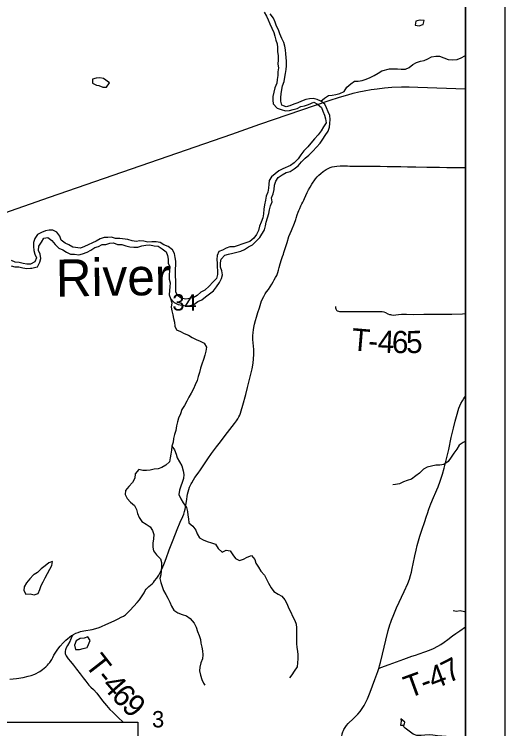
# Model space of a CAD drawing. Extents: x -7.5 to 53.5, y 0 to 22.
# Drawn here: x 7.745 to 9, y 16.725 to 18.553 of the extents above; entities that cross this region are included whole.
import ezdxf

# ---------------------------------------------------------------- set-up
doc = ezdxf.new("R2010")
doc.units = 0
for name, color, linetype in [('GM_X_Corporation', 7, 'Continuous'), ('GM_X_Major_River', 7, 'Continuous'), ('GM_X_Major_River_Text', 7, 'Continuous'), ('GM_X_Minor_Lake', 7, 'Continuous'), ('GM_X_Minor_River', 7, 'Continuous'), ('GM_X_Rail_Line', 7, 'Continuous'), ('GM_X_Section_Text', 7, 'Continuous'), ('GM_X_Township_Road', 7, 'Continuous'), ('GM_X_Township_Road_Text', 7, 'Continuous'), ('SH_Data', 7, 'Continuous'), ('SH_Text', 7, 'Continuous')]:
    doc.layers.add(name, color=color, linetype=linetype)

msp = doc.modelspace()

# ---------------------------------------------------------------- linework, layer by layer
at = {"layer": 'GM_X_Corporation'}
msp.add_lwpolyline([(8.9, 14.1), (8.9, 19.1887), (8.5159, 19.1718), (8.414, 19.1709), (7.544, 19.1455), (6.5522, 19.1561), (6.0433, 19.1527), (6.0424, 19.1527), (5.0411, 19.1401), (4.5565, 19.1354), (4.5696, 18.2604), (4.5718, 18.1276), (4.5771, 17.6201), (4.5749, 17.2575), (4.577, 17.1178), (4.5822, 16.8992), (4.5826, 16.8462), (4.5872, 16.3635), (4.5873, 16.3533), (4.594, 15.8096), (4.6021, 15.6139), (4.6087, 14.5302)], dxfattribs=at)
at = {"layer": 'GM_X_Major_River'}
for points in [[(8.3844, 18.5588), (8.3904, 18.5489), (8.3949, 18.5394), (8.399, 18.5287), (8.4038, 18.5181), (8.4094, 18.507), (8.4112, 18.4975), (8.4138, 18.4876), (8.4171, 18.4778), (8.4182, 18.4683), (8.4181, 18.458), (8.4203, 18.447), (8.4202, 18.4371), (8.4193, 18.4258), (8.4208, 18.4163), (8.4188, 18.4061), (8.4195, 18.3966), (8.4175, 18.3867), (8.4163, 18.3769), (8.4116, 18.3656), (8.4093, 18.3546), (8.4061, 18.3432), (8.4064, 18.3337), (8.4075, 18.3243), (8.4173, 18.3135), (8.4278, 18.3097), (8.4388, 18.3065), (8.4491, 18.3076), (8.4586, 18.3098), (8.4684, 18.3123), (8.4783, 18.3172), (8.4878, 18.3194), (8.4981, 18.3223), (8.511, 18.3282), (8.5208, 18.3236), (8.5314, 18.3148), (8.5347, 18.3053), (8.5384, 18.2954), (8.541, 18.2859), (8.5432, 18.276), (8.5363, 18.2658), (8.5301, 18.2553), (8.5224, 18.2451), (8.5129, 18.2349), (8.5037, 18.224), (8.4957, 18.2139), (8.4861, 18.2041), (8.4777, 18.1939), (8.4715, 18.1834), (8.4608, 18.1732), (8.4513, 18.1669), (8.4323, 18.1579), (8.422, 18.1527), (8.4125, 18.1456), (8.4029, 18.1377), (8.3968, 18.1279), (8.3963, 18.1184), (8.3955, 18.1082), (8.3939, 18.0984), (8.3896, 18.0878), (8.3876, 18.0779), (8.3853, 18.0662), (8.3833, 18.0545), (8.3828, 18.0431), (8.3812, 18.0325), (8.3769, 18.0215), (8.3727, 18.011), (8.3699, 18), (8.3646, 17.9902), (8.3577, 17.9804), (8.3474, 17.9725), (8.3371, 17.9684), (8.3268, 17.9655), (8.3173, 17.9622), (8.3078, 17.9584), (8.2964, 17.9582), (8.2869, 17.9552), (8.2774, 17.95), (8.2679, 17.9467), (8.264, 17.9361), (8.2632, 17.9262), (8.2639, 17.9168), (8.2642, 17.9069), (8.2649, 17.8974), (8.2652, 17.8875), (8.2624, 17.8777), (8.2532, 17.8679), (8.2433, 17.8578), (8.2326, 17.8473), (8.2223, 17.8424), (8.2128, 17.8342), (8.2025, 17.8282), (8.1835, 17.8246), (8.1722, 17.8269), (8.162, 17.8339), (8.1579, 17.8434), (8.158, 17.8529), (8.1584, 17.8623), (8.1578, 17.873), (8.1571, 17.8824)], [(8.5531, 18.2843), (8.5524, 18.2941), (8.548, 18.3036), (8.5435, 18.3139), (8.5398, 18.3234), (8.5296, 18.3311), (8.5198, 18.335), (8.51, 18.3381), (8.5001, 18.3371), (8.4906, 18.3353), (8.48, 18.3308), (8.4701, 18.3271), (8.4602, 18.3238), (8.4503, 18.3193), (8.4408, 18.3167), (8.4298, 18.3206), (8.4265, 18.3309), (8.4273, 18.3404), (8.4278, 18.3499), (8.4298, 18.3608), (8.4314, 18.3707), (8.4353, 18.3816), (8.4369, 18.3922), (8.4385, 18.4021), (8.4408, 18.4119), (8.4413, 18.4218), (8.4414, 18.4335), (8.4407, 18.443), (8.4393, 18.4525), (8.439, 18.4624), (8.4368, 18.4719), (8.4342, 18.4814), (8.4297, 18.4917), (8.4242, 18.5035), (8.4212, 18.5134), (8.416, 18.5233), (8.4123, 18.5332), (8.4078, 18.5434), (8.3996, 18.5549)], [(7.8406, 17.9748), (7.8489, 17.9645), (7.8586, 17.9549), (7.8685, 17.9507), (7.8783, 17.9445), (7.8888, 17.9395), (7.8987, 17.9394), (7.9097, 17.9378), (7.9192, 17.9407), (7.9313, 17.9452), (7.9408, 17.9496), (7.9504, 17.9564), (7.9599, 17.9593), (7.9694, 17.9645), (7.9792, 17.9641), (7.9891, 17.9682), (7.9986, 17.9688), (8.0092, 17.9646), (8.0198, 17.9641), (8.03, 17.9606), (8.0406, 17.9586), (8.0505, 17.9577), (8.0611, 17.958), (8.0709, 17.9613), (8.0816, 17.9624), (8.0918, 17.9634), (8.1028, 17.9607), (8.1126, 17.9598), (8.1232, 17.9537), (8.133, 17.946), (8.1367, 17.9365), (8.1381, 17.9266), (8.1388, 17.9164), (8.1425, 17.9069), (8.1417, 17.8974), (8.1408, 17.8868), (8.1407, 17.8758), (8.1437, 17.8663), (8.1429, 17.8564), (8.1416, 17.8466), (8.1408, 17.836), (8.1445, 17.8261), (8.1539, 17.8161), (8.1641, 17.8111), (8.1747, 17.8091), (8.1845, 17.8075), (8.1944, 17.8085), (8.2039, 17.8111), (8.2145, 17.8182), (8.2244, 17.8231), (8.2344, 17.8302), (8.2542, 17.8459), (8.2622, 17.8565), (8.2695, 17.8674), (8.2749, 17.8772), (8.2773, 17.8871), (8.2758, 17.8973), (8.2721, 17.9068), (8.2726, 17.9171), (8.2742, 17.9273), (8.2838, 17.9367), (8.2933, 17.9396), (8.3043, 17.9426), (8.3145, 17.9451), (8.3244, 17.9473), (8.3343, 17.9518), (8.3438, 17.9581), (8.3541, 17.9637), (8.3637, 17.9731), (8.3732, 17.9821), (8.3847, 18.0017), (8.3875, 18.012), (8.3891, 18.0218), (8.3926, 18.0328), (8.3965, 18.0433), (8.3981, 18.0532), (8.4004, 18.0634), (8.4043, 18.0732), (8.4029, 18.0842), (8.4075, 18.0944), (8.4099, 18.1054), (8.4103, 18.116), (8.4142, 18.1262), (8.4203, 18.136), (8.4299, 18.1424), (8.4409, 18.1484), (8.4504, 18.1513), (8.4611, 18.1577), (8.471, 18.1659), (8.4794, 18.1757), (8.489, 18.1855), (8.4985, 18.1934), (8.5088, 18.2031), (8.518, 18.2137), (8.5272, 18.2234), (8.5345, 18.2336), (8.5406, 18.2434), (8.5479, 18.2543), (8.5518, 18.2649), (8.5523, 18.2744), (8.5531, 18.2843)], [(7.9539, 17.973), (7.9444, 17.9686), (7.9338, 17.9637), (7.9242, 17.9589), (7.9144, 17.9552), (7.8947, 17.9576), (7.8845, 17.9638), (7.8747, 17.9677), (7.8645, 17.9757), (7.8615, 17.9856), (7.8537, 17.9959), (7.8435, 18.0013), (7.834, 18.001), (7.8245, 17.9992), (7.8139, 17.9955), (7.8043, 17.9899), (7.7974, 17.9801), (7.7936, 17.9699), (7.7939, 17.9589), (7.7949, 17.9494), (7.7971, 17.9399), (7.8016, 17.9304), (7.7973, 17.9202), (7.7863, 17.9142), (7.7768, 17.9139), (7.767, 17.9159), (7.7571, 17.9183), (7.7469, 17.9195), (7.7371, 17.9234)], [(7.7995, 17.9062), (7.8037, 17.9076), (7.8098, 17.919), (7.8122, 17.9288), (7.8111, 17.9398), (7.8063, 17.9493), (7.8071, 17.9603), (7.814, 17.9705), (7.8206, 17.9807), (7.8301, 17.9825), (7.8406, 17.9748)], [(8.1571, 17.8824), (8.1575, 17.8919), (8.1576, 17.9014), (8.1585, 17.912), (8.1582, 17.9219), (8.156, 17.9314), (8.1545, 17.9413), (8.1493, 17.9508), (8.1384, 17.9596), (8.1278, 17.9639), (8.118, 17.9693), (8.1078, 17.9713), (8.0968, 17.971), (8.0862, 17.9707), (8.076, 17.9731), (8.0657, 17.9735), (8.0563, 17.9717), (8.046, 17.9737), (8.0351, 17.9772), (8.0146, 17.9797), (8.0036, 17.9798), (7.9938, 17.9829), (7.9843, 17.9826), (7.9745, 17.9819), (7.9646, 17.9786), (7.9539, 17.973)], [(7.7366, 17.9094), (7.7464, 17.9074), (7.7563, 17.9069), (7.7661, 17.9046), (7.7767, 17.903), (7.7862, 17.9036), (7.7873, 17.904)], [(7.7873, 17.904), (7.7892, 17.9036), (7.7995, 17.9062)]]:
    msp.add_lwpolyline(points, dxfattribs=at)
at = {"layer": 'GM_X_Minor_Lake'}
for points in [[(8.7826, 18.5385), (8.7727, 18.5356), (8.7708, 18.5258), (8.7806, 18.5241), (8.7901, 18.5271), (8.7909, 18.5275)], [(8.7909, 18.5275), (8.794, 18.5373), (8.7838, 18.5385), (8.7826, 18.5385)], [(7.9733, 18.3892), (7.9635, 18.3908), (7.954, 18.3902), (7.9445, 18.3872), (7.9448, 18.3774), (7.955, 18.3723), (7.961, 18.3715)], [(7.961, 18.3715), (7.9712, 18.3669), (7.9807, 18.3668), (7.988, 18.3777), (7.9733, 18.3892)], [(7.8097, 17.0813), (7.8136, 17.0918), (7.8182, 17.1017), (7.8236, 17.1115), (7.8294, 17.1228), (7.8355, 17.1334), (7.8409, 17.1432), (7.8425, 17.153), (7.833, 17.1501), (7.8235, 17.1426), (7.8132, 17.1347), (7.8044, 17.1249), (7.7956, 17.1197)], [(7.7956, 17.1197), (7.7937, 17.1189), (7.7842, 17.1092), (7.7761, 17.099), (7.7703, 17.0888), (7.7688, 17.079), (7.774, 17.0695), (7.7854, 17.0705), (7.7956, 17.0681), (7.8058, 17.0714), (7.8097, 17.0813)], [(7.9129, 16.9563), (7.9034, 16.95), (7.8984, 16.939), (7.9013, 16.9284), (7.9115, 16.9283), (7.921, 16.9305), (7.9309, 16.9334), (7.9321, 16.9349)], [(7.9321, 16.9349), (7.9386, 16.9512), (7.933, 16.9607), (7.9231, 16.9574), (7.9129, 16.9563)], [(8.7344, 16.7506), (8.7351, 16.7445), (8.7332, 16.7347), (8.7426, 16.7346)], [(8.7426, 16.7346), (8.7442, 16.7425), (8.7344, 16.7506)]]:
    msp.add_lwpolyline(points, dxfattribs=at)
at = {"layer": 'GM_X_Minor_River'}
for points in [[(8.5296, 18.3311), (8.5391, 18.339), (8.5487, 18.3454), (8.5582, 18.3464), (8.5677, 18.3478), (8.5783, 18.3508), (8.5886, 18.356), (8.5962, 18.3673), (8.6058, 18.3759), (8.6153, 18.3823), (8.6248, 18.3826), (8.6354, 18.3844), (8.6453, 18.3873), (8.6556, 18.3914), (8.6658, 18.397), (8.6761, 18.4026), (8.6857, 18.409), (8.7047, 18.4141), (8.7156, 18.4136), (8.7255, 18.4135), (8.7353, 18.4131), (8.7456, 18.413), (8.7551, 18.4171), (8.765, 18.4246), (8.7745, 18.4302), (8.784, 18.4335), (8.7935, 18.4353), (8.8034, 18.4398), (8.8129, 18.4446), (8.8236, 18.4464), (8.833, 18.4463), (8.8444, 18.442), (8.8553, 18.4381), (8.8667, 18.4369), (8.8781, 18.4379), (8.8883, 18.4424), (8.8979, 18.4472), (8.9, 18.4475)], [(8.1445, 17.8261), (8.1478, 17.8154), (8.1466, 17.8044), (8.1476, 17.7946), (8.1502, 17.7847), (8.152, 17.7748), (8.1546, 17.7653), (8.1557, 17.7558), (8.1598, 17.7463), (8.17, 17.742), (8.1798, 17.737), (8.1903, 17.7327), (8.2001, 17.7266), (8.2103, 17.7212), (8.2205, 17.7169), (8.2307, 17.7119), (8.2367, 17.702), (8.2351, 17.6918), (8.232, 17.6815), (8.2289, 17.6702), (8.2246, 17.6585), (8.2215, 17.6479), (8.2184, 17.6365), (8.2152, 17.6263), (8.2125, 17.6165), (8.2079, 17.6055), (8.2036, 17.595), (8.1974, 17.5836), (8.1913, 17.5738), (8.1863, 17.5633), (8.1805, 17.5523), (8.1736, 17.5418), (8.1697, 17.5312), (8.1651, 17.5202), (8.162, 17.5104), (8.1596, 17.5006), (8.158, 17.4884), (8.1545, 17.4782), (8.1521, 17.4684), (8.1513, 17.4589), (8.1482, 17.4483), (8.1473, 17.4381), (8.145, 17.4283), (8.1434, 17.4184), (8.1422, 17.4086), (8.1322, 17.3999), (8.1227, 17.3939), (8.1125, 17.3902), (8.1026, 17.3892), (8.0927, 17.3874), (8.0829, 17.3863), (8.0734, 17.3864), (8.0635, 17.3884), (8.0544, 17.3779), (8.0528, 17.3665), (8.0474, 17.3556), (8.0374, 17.3454), (8.0297, 17.3349), (8.0281, 17.3246), (8.0334, 17.3147), (8.042, 17.3052), (8.0525, 17.2964), (8.0574, 17.2865), (8.06, 17.2758), (8.064, 17.2655), (8.0708, 17.256), (8.0821, 17.2487), (8.0927, 17.2421), (8.0983, 17.2322), (8.1016, 17.2223), (8.1007, 17.211), (8.0991, 17.2004), (8.0994, 17.1901), (8.1012, 17.1806), (8.1087, 17.17), (8.1185, 17.1604), (8.1215, 17.1509), (8.1214, 17.1406), (8.1205, 17.1304), (8.1197, 17.1194), (8.117, 17.1096), (8.1195, 17.0993), (8.1228, 17.0894), (8.1266, 17.0795), (8.1325, 17.0692), (8.1374, 17.0597), (8.143, 17.0491), (8.1474, 17.0392), (8.153, 17.0289), (8.1632, 17.0223), (8.1746, 17.0177), (8.1851, 17.0142), (8.1949, 17.0072), (8.2047, 16.9958), (8.2099, 16.9851), (8.2132, 16.9745), (8.2181, 16.9638), (8.221, 16.9535), (8.2221, 16.9441), (8.225, 16.9345), (8.2265, 16.9251)], [(8.9, 17.461), (8.8934, 17.4579), (8.8835, 17.4508), (8.8774, 17.441), (8.8697, 17.4304), (8.8632, 17.4199), (8.8551, 17.4089), (8.8445, 17.4018), (8.8342, 17.4), (8.824, 17.3994), (8.8126, 17.3972), (8.8019, 17.3946), (8.792, 17.3894), (8.7817, 17.3796), (8.7722, 17.3725), (8.7611, 17.3639), (8.7505, 17.3606), (8.7406, 17.3569), (8.7307, 17.3517), (8.7208, 17.3499), (8.714, 17.3492)], [(8.1482, 17.4483), (8.1549, 17.4388), (8.159, 17.4281), (8.1616, 17.4186), (8.1679, 17.4087), (8.1735, 17.3977), (8.1772, 17.3855), (8.1787, 17.376), (8.1778, 17.3658), (8.1747, 17.3556), (8.1712, 17.3457), (8.1673, 17.3355), (8.1654, 17.3245), (8.1709, 17.3135), (8.1773, 17.3036), (8.1852, 17.2914), (8.1881, 17.2815), (8.1892, 17.2716), (8.1906, 17.2621), (8.1917, 17.2526), (8.2018, 17.2434), (8.2097, 17.2339), (8.213, 17.224), (8.2186, 17.2141), (8.2284, 17.2087), (8.2387, 17.2048), (8.2492, 17.2013), (8.2594, 17.1974), (8.2669, 17.1863), (8.2767, 17.1772), (8.287, 17.182), (8.2968, 17.1808), (8.3039, 17.1705), (8.3111, 17.1609), (8.3209, 17.1559), (8.3315, 17.1596), (8.341, 17.1648), (8.3517, 17.1685), (8.3607, 17.1586), (8.3629, 17.1491), (8.3696, 17.1392), (8.376, 17.1289), (8.3854, 17.1182), (8.3902, 17.1083), (8.3951, 17.098), (8.4018, 17.0862), (8.4093, 17.0766), (8.4198, 17.0701), (8.4297, 17.0647), (8.4375, 17.0551), (8.4428, 17.0444), (8.4468, 17.0349), (8.4521, 17.0235), (8.4565, 17.0136), (8.4625, 17.0026), (8.4658, 16.993), (8.4669, 16.9832), (8.4672, 16.9733), (8.4667, 16.9638), (8.4666, 16.9536), (8.4669, 16.9434), (8.468, 16.9331), (8.4694, 16.9236), (8.4701, 16.9141), (8.4704, 16.9043), (8.4696, 16.8944), (8.4691, 16.8834), (8.4614, 16.8729), (8.4549, 16.8631), (8.4491, 16.8555)], [(8.9, 17.0248), (8.897, 17.0248), (8.8861, 17.0272), (8.8762, 17.0257), (8.8679, 17.027)], [(8.2265, 16.9251), (8.2275, 16.9144), (8.2267, 16.9042), (8.2221, 16.894), (8.2193, 16.8826), (8.2185, 16.8732), (8.2214, 16.8621), (8.2247, 16.8515), (8.2288, 16.8416), (8.2322, 16.8366)], [(8.9, 16.7003), (8.8936, 16.6998), (8.8822, 16.6996), (8.8724, 16.7004), (8.861, 16.7032), (8.8504, 16.7059), (8.8387, 16.706), (8.8277, 16.7076), (8.8163, 16.7093), (8.8065, 16.7097), (8.7959, 16.7091), (8.7864, 16.708), (8.7754, 16.7081), (8.7656, 16.7112), (8.755, 16.7193), (8.7452, 16.7266), (8.738, 16.7346)]]:
    msp.add_lwpolyline(points, dxfattribs=at)
at = {"layer": 'GM_X_Rail_Line'}
msp.add_lwpolyline([(7.7029, 18.0394), (7.835, 18.0853), (8.3014, 18.2469), (8.3734, 18.2719), (8.5509, 18.3328), (8.577, 18.3414), (8.598, 18.3475), (8.612, 18.3512), (8.6268, 18.3548), (8.6406, 18.3578), (8.6579, 18.3607), (8.6735, 18.363), (8.6921, 18.3652), (8.7109, 18.3666), (8.7359, 18.3675), (8.7554, 18.3676), (8.7774, 18.3673), (8.9, 18.363)], dxfattribs=at)
at = {"layer": 'GM_X_Township_Road'}
for points in [[(7.8933, 16.9648), (7.8965, 16.9668), (7.902, 16.9696), (7.9077, 16.972), (7.9137, 16.9738), (7.9227, 16.9759), (7.9442, 16.9795), (7.9533, 16.9815), (7.9622, 16.9843), (7.9679, 16.9866), (7.9791, 16.992), (7.9846, 16.9949), (8.0016, 17.0027), (8.0101, 17.0065), (8.0184, 17.0106), (8.0238, 17.0137), (8.0289, 17.0171), (8.0337, 17.0211), (8.0403, 17.0276), (8.051, 17.0388), (8.0593, 17.0481), (8.0652, 17.0553), (8.0706, 17.0629), (8.0771, 17.0735), (8.08, 17.0788), (8.0826, 17.0828), (8.0861, 17.0869), (8.0888, 17.0897), (8.0934, 17.0931), (8.0972, 17.0961), (8.1007, 17.0994), (8.1039, 17.1035), (8.1095, 17.1109), (8.1146, 17.1187), (8.1191, 17.1269), (8.1231, 17.1353), (8.1291, 17.1496), (8.1336, 17.1613), (8.141, 17.1831), (8.1515, 17.2091), (8.1618, 17.2354), (8.1693, 17.2542), (8.1759, 17.2681), (8.1782, 17.2742), (8.1804, 17.2813), (8.1817, 17.2871), (8.1851, 17.3069), (8.1883, 17.3256), (8.1896, 17.3317), (8.1912, 17.3376), (8.1933, 17.3434), (8.1958, 17.349), (8.1973, 17.3517), (8.1989, 17.3547), (8.2032, 17.362), (8.2071, 17.3684), (8.215, 17.3794), (8.2211, 17.3878), (8.2318, 17.4029), (8.2404, 17.4163), (8.2494, 17.4296), (8.2623, 17.4467), (8.2724, 17.4592), (8.2846, 17.476), (8.3083, 17.5065), (8.3135, 17.5134), (8.3168, 17.5187), (8.3193, 17.5231), (8.3217, 17.528), (8.3234, 17.5325), (8.3257, 17.5385), (8.33, 17.5533), (8.3374, 17.5803), (8.342, 17.5984), (8.3468, 17.6187), (8.3535, 17.6467), (8.3552, 17.6558), (8.356, 17.662), (8.3568, 17.6713), (8.3575, 17.6838), (8.3575, 17.6954), (8.3554, 17.721), (8.3553, 17.7303), (8.3559, 17.7396), (8.3566, 17.7457), (8.3577, 17.7518), (8.3597, 17.7608), (8.3621, 17.7697), (8.3647, 17.7786), (8.3684, 17.7904), (8.3719, 17.8027), (8.3776, 17.8205), (8.383, 17.8314), (8.387, 17.8379), (8.3906, 17.8434), (8.395, 17.8494), (8.3994, 17.8558), (8.4036, 17.8625), (8.4074, 17.8689), (8.4101, 17.8739), (8.4136, 17.8798), (8.4165, 17.8855), (8.4193, 17.8929), (8.421, 17.8988), (8.4229, 17.9054), (8.4256, 17.9151), (8.4289, 17.926), (8.4315, 17.9337), (8.4335, 17.9398), (8.4349, 17.9439), (8.4384, 17.9544), (8.4432, 17.9697), (8.4478, 17.9846), (8.4542, 18.0002), (8.4617, 18.0192), (8.4649, 18.0286), (8.466, 18.0316), (8.4689, 18.04), (8.4715, 18.0468), (8.4734, 18.0517), (8.4757, 18.0568), (8.4783, 18.063), (8.4808, 18.0682), (8.4832, 18.0729), (8.4854, 18.0775), (8.4874, 18.0822), (8.4905, 18.0897), (8.4944, 18.0977), (8.498, 18.1047), (8.502, 18.1115), (8.5061, 18.1187), (8.5094, 18.1236), (8.5122, 18.1277), (8.5156, 18.1322), (8.5203, 18.1377), (8.5244, 18.142), (8.529, 18.1464), (8.5353, 18.1516), (8.5426, 18.1565), (8.5478, 18.159), (8.5531, 18.1611), (8.5587, 18.1629), (8.5644, 18.1642), (8.5703, 18.165), (8.5792, 18.1656), (8.5879, 18.1655), (8.5943, 18.1655), (8.5973, 18.1654), (8.6035, 18.1652), (8.6208, 18.1651), (8.6354, 18.1649), (8.6501, 18.1648), (8.6655, 18.1647), (8.6816, 18.1645), (8.6992, 18.1644), (8.716, 18.1642), (8.7252, 18.164), (8.7341, 18.1638), (8.7513, 18.1634), (8.7722, 18.1629), (8.801, 18.1622), (8.8186, 18.1621), (8.8331, 18.1619), (8.8517, 18.1618), (8.8748, 18.1616), (8.9, 18.1614)], [(8.5668, 17.8055), (8.567, 17.8024), (8.5676, 17.7994), (8.5691, 17.7967), (8.5714, 17.7947), (8.5743, 17.7935), (8.5773, 17.7929), (8.5804, 17.7927), (8.6053, 17.7926), (8.6458, 17.7927), (8.68, 17.7932), (8.6864, 17.7928), (8.6908, 17.792), (8.6951, 17.7907), (8.701, 17.7874), (8.7052, 17.7856), (8.7074, 17.785), (8.7101, 17.7843), (8.7147, 17.7838), (8.7217, 17.7843), (8.7278, 17.7856), (8.7354, 17.7861), (8.7485, 17.7863), (8.7658, 17.7857), (8.7929, 17.7859), (8.8209, 17.7861), (8.8396, 17.7861), (8.8539, 17.7862), (8.8649, 17.7865), (8.8916, 17.7872), (8.9, 17.7875)], [(8.6775, 16.8799), (8.6795, 16.8862), (8.6819, 16.8952), (8.687, 16.9163), (8.6956, 16.9524), (8.7017, 16.9765), (8.706, 16.9914), (8.7081, 16.9977), (8.7101, 17.0031), (8.7158, 17.0176), (8.7233, 17.0346), (8.743, 17.0768), (8.7518, 17.0967), (8.7563, 17.1083), (8.7591, 17.1171), (8.7615, 17.1261), (8.7635, 17.135), (8.7658, 17.147), (8.7698, 17.1678), (8.773, 17.1827), (8.7758, 17.1946), (8.7791, 17.2065), (8.7827, 17.2183), (8.7885, 17.236), (8.7947, 17.2535), (8.7999, 17.2695), (8.8021, 17.2763), (8.8057, 17.287), (8.8084, 17.2943), (8.8108, 17.3008), (8.8176, 17.3172), (8.8234, 17.3304), (8.8261, 17.3365), (8.8296, 17.3446), (8.8349, 17.3591), (8.8406, 17.3769), (8.845, 17.3918), (8.8504, 17.4128), (8.8566, 17.4401), (8.8632, 17.4704), (8.8687, 17.4946), (8.8731, 17.5127), (8.8779, 17.5306), (8.8807, 17.5395), (8.8826, 17.5454), (8.8851, 17.5515), (8.888, 17.5572), (8.8918, 17.5641), (8.8956, 17.5705), (8.9, 17.5766)], [(8.6775, 16.8799), (8.683, 16.8819), (8.7041, 16.8896), (8.7418, 16.9032), (8.7622, 16.9108), (8.772, 16.914), (8.7806, 16.9171), (8.7958, 16.9225), (8.8072, 16.9266), (8.8176, 16.9306), (8.8289, 16.9365), (8.8361, 16.941), (8.8449, 16.9472), (8.8541, 16.9539), (8.8667, 16.9631), (8.8749, 16.9688), (8.8852, 16.9757), (8.9, 16.986)], [(7.7336, 16.8524), (7.7501, 16.8542), (7.7674, 16.8566), (7.7803, 16.8596), (7.788, 16.8612), (7.7972, 16.8647), (7.81, 16.8719), (7.8171, 16.8769), (7.8254, 16.8835), (7.8295, 16.8883), (7.8324, 16.8911), (7.8354, 16.8945), (7.8373, 16.8972), (7.8404, 16.9025), (7.8433, 16.9079), (7.8462, 16.9134), (7.8492, 16.9189), (7.8524, 16.9242), (7.8559, 16.9293), (7.8617, 16.9364), (7.8701, 16.9454), (7.8767, 16.9519), (7.8813, 16.9561), (7.8861, 16.96), (7.8912, 16.9636), (7.8933, 16.9648)], [(7.8933, 16.9648), (7.8903, 16.9573), (7.8892, 16.9545), (7.888, 16.9517), (7.8866, 16.949), (7.8807, 16.9382), (7.8777, 16.9328), (7.8765, 16.9299), (7.8755, 16.927), (7.875, 16.924), (7.8748, 16.9209), (7.8751, 16.9179), (7.8759, 16.915), (7.8772, 16.9122), (7.8788, 16.9095), (7.8825, 16.9045), (7.8885, 16.8974), (7.8965, 16.8879), (7.9042, 16.8782), (7.9136, 16.8659), (7.9208, 16.8559), (7.9276, 16.847), (7.9357, 16.8369), (7.9405, 16.8318), (7.9474, 16.8256), (7.9559, 16.8163), (7.9705, 16.7968), (7.9803, 16.7849), (7.9893, 16.7748), (7.9966, 16.7674), (8.0111, 16.7537), (8.0222, 16.7433), (8.0238, 16.7419)], [(8.5915, 16.7289), (8.5953, 16.7339), (8.5995, 16.7384), (8.6127, 16.7516), (8.6236, 16.7627), (8.6297, 16.7697), (8.6354, 16.7771), (8.6404, 16.7849), (8.6447, 16.7932), (8.6484, 16.8017), (8.6552, 16.8191), (8.6674, 16.851), (8.6748, 16.8715), (8.6775, 16.8799)], [(8.5833, 16.6853), (8.5831, 16.6965), (8.5834, 16.7058), (8.5842, 16.712), (8.5849, 16.715), (8.5859, 16.7179), (8.587, 16.7208), (8.5883, 16.7236), (8.5898, 16.7264), (8.5915, 16.7289)]]:
    msp.add_lwpolyline(points, dxfattribs=at)
at = {"layer": 'SH_Data'}
for p, q in [((9, 21), (9, 14)), ((8.9, 20.9), (8.9, 14.1))]:
    msp.add_line(p, q, dxfattribs=at)
at = {"layer": 'SH_Text'}
msp.add_lwpolyline([(6.5259, 16.7419), (8.061, 16.7419), (8.061, 16.1744), (6.5259, 16.1744)], close=True, dxfattribs=at)

# ---------------------------------------------------------------- texts
at = {"layer": 'GM_X_Major_River_Text'}
msp.add_text('River', height=0.09471, rotation=0.8813, dxfattribs=at).set_placement((7.8516, 17.831))
at = {"layer": 'GM_X_Section_Text'}
for s, height, p in [('34', 0.04186, (8.1492, 17.7954)), ('3', 0.0419, (8.0972, 16.7288))]:
    msp.add_text(s, height=height, rotation=0, dxfattribs=at).set_placement(p)
at = {"layer": 'GM_X_Township_Road_Text'}
for s, rotation, p in [('T', 355.0997, (8.6059, 17.6941)), ('4', 357.2763, (8.6739, 17.6885)), ('6', 359.2132, (8.7109, 17.6868)), ('5', 1.0514, (8.7479, 17.6863)), ('-', 355.7054, (8.6489, 17.6904)), ('T', 307.9242, (7.9232, 16.8892)), ('7', 27.1602, (8.8562, 16.8409)), ('4', 20.7393, (8.8171, 16.8257)), ('-', 309.7253, (7.9506, 16.8542)), ('T', 19.9842, (8.7545, 16.8029)), ('4', 310.9595, (7.9663, 16.8352)), ('6', 312.4899, (7.9904, 16.8075)), ('-', 20.114, (8.7946, 16.8174)), ('9', 315.884, (8.0166, 16.7791))]:
    msp.add_text(s, height=0.0568, rotation=rotation, dxfattribs=at).set_placement(p)

doc.saveas('drawing.dxf')
